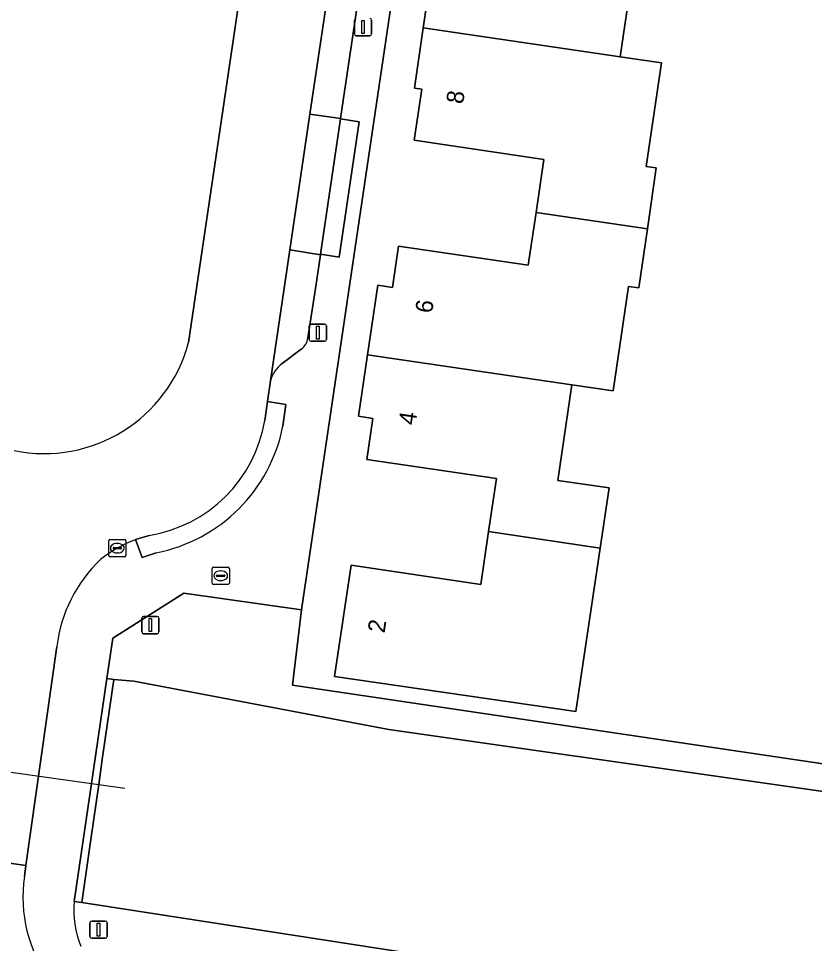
# Model space of a CAD drawing. Extents: x 164148 to 165261, y 382513 to 383432.
# Drawn here: x 164462.2 to 164508.4, y 382861.7 to 382915.4 of the extents above; entities that cross this region are included whole.
import ezdxf

# ---------------------------------------------------------------- set-up
doc = ezdxf.new("R2010")
doc.units = 0
for name, color, linetype in [('IMGEO_Duiker', 7, 'Continuous'), ('IMGEO_Erf', 7, 'Continuous'), ('IMGEO_Greppel_droge_sloot', 7, 'Continuous'), ('IMGEO_Groenvoorziening', 7, 'Continuous'), ('IMGEO_Kolk', 7, 'Continuous'), ('IMGEO_Lichtmast', 7, 'Continuous'), ('IMGEO_Muur', 7, 'Continuous'), ('IMGEO_Pand', 7, 'Continuous'), ('IMGEO_Pand_nummerreeks', 7, 'Continuous'), ('IMGEO_Parkeervlak_open', 7, 'Continuous'), ('IMGEO_Rijbaan_lokaal_open', 7, 'Continuous'), ('IMGEO_Rioolput', 7, 'Continuous'), ('IMGEO_Voetpad_open', 7, 'Continuous')]:
    doc.layers.add(name, color=color, linetype=linetype)

msp = doc.modelspace()

# ---------------------------------------------------------------- linework, layer by layer
at = {"layer": 'IMGEO_Duiker'}
msp.add_lwpolyline([(164452.014, 382872.996), (164453.522, 382872.784), (164453.949, 382872.723), (164466.481, 382870.957), (164466.901, 382870.898), (164468.418, 382870.684)], dxfattribs=at)
at = {"layer": 'IMGEO_Erf'}
msp.add_lwpolyline([(164536.67, 382930.425), (164544.133, 382980.726), (164542.913, 382982.243), (164519.298, 382985.737), (164495.986, 382989.176), (164494.523, 382988.072), (164478.67, 382881.048), (164478.137, 382876.668), (164527.73, 382869.322)], close=True, dxfattribs=at)
msp.add_lwpolyline([(164497.979, 382918.699), (164497.165, 382913.157), (164499.559, 382912.806), (164498.667, 382906.787), (164499.262, 382906.703), (164498.744, 382903.179), (164498.239, 382899.743), (164497.643, 382899.83), (164496.751, 382893.761), (164494.362, 382894.113), (164493.546, 382888.557), (164496.524, 382888.13), (164496.004, 382884.636), (164494.589, 382875.139), (164480.59, 382877.186), (164481.556, 382883.642), (164489.074, 382882.518), (164489.527, 382885.591), (164489.98, 382888.664), (164482.461, 382889.777), (164482.816, 382892.167), (164481.973, 382892.292), (164482.501, 382895.861), (164483.098, 382899.895), (164483.946, 382899.769), (164484.301, 382902.158), (164491.833, 382901.054), (164492.284, 382904.127), (164492.734, 382907.199), (164485.215, 382908.319), (164485.647, 382911.272), (164485.222, 382911.337), (164485.737, 382914.833), (164486.177, 382917.822)], dxfattribs=at)
at = {"layer": 'IMGEO_Greppel_droge_sloot'}
msp.add_lwpolyline([(164527.808, 382867.71), (164528.242, 382867.643), (164528.255, 382867.732), (164527.513, 382867.841), (164483.733, 382874.094), (164468.94, 382876.903), (164467.772, 382876.998), (164467.128, 382872.489), (164466.901, 382870.898), (164466.447, 382867.72), (164465.924, 382864.054), (164484.051, 382861.245), (164524.835, 382854.782), (164525.957, 382854.773), (164526.609, 382859.328), (164526.913, 382861.453), (164527.19, 382863.393)], close=True, dxfattribs=at)
at = {"layer": 'IMGEO_Groenvoorziening'}
for points in [[(164472.108, 382896.577), (164486.03, 382990.645)], [(164465.924, 382864.054), (164465.481, 382864.11)], [(164526.374, 382854.707), (164525.957, 382854.773), (164524.835, 382854.782), (164484.051, 382861.245), (164465.924, 382864.054)]]:
    msp.add_lwpolyline(points, dxfattribs=at)
msp.add_lwpolyline([(164478.137, 382876.668), (164478.67, 382881.048), (164471.849, 382882.015), (164467.712, 382879.403), (164467.374, 382877.067), (164467.772, 382876.998), (164468.94, 382876.903), (164483.733, 382874.094), (164527.513, 382867.841), (164527.73, 382869.322)], close=True, dxfattribs=at)
for centre, radius, start, end in [((164463.736, 382898.773), 8.655, 258.3612, 345.3007), ((164470.735, 382863.571), 5.282, 174.1455, 202.9355)]:
    msp.add_arc(centre, radius, start, end, dxfattribs=at)
at = {"layer": 'IMGEO_Kolk'}
for p, q in [((164467.478, 382884.202), (164467.478, 382885.054)), ((164467.553, 382885.128), (164468.405, 382885.128)), ((164467.966, 382884.908), (164467.991, 382884.908)), ((164468.479, 382885.054), (164468.479, 382884.202)), ((164467.737, 382884.622), (164467.737, 382884.634)), ((164468.175, 382884.585), (164467.777, 382884.585)), ((164467.78, 382884.671), (164468.178, 382884.671)), ((164467.989, 382884.348), (164467.964, 382884.348)), ((164468.221, 382884.634), (164468.221, 382884.622)), ((164468.405, 382884.128), (164467.553, 382884.128))]:
    msp.add_line(p, q, dxfattribs=at)
for points in [[(164467.478, 382884.202), (164467.478, 382885.054)], [(164467.553, 382885.128), (164468.405, 382885.128)], [(164468.479, 382885.054), (164468.479, 382884.202)], [(164468.405, 382884.128), (164467.553, 382884.128)]]:
    msp.add_lwpolyline(points, dxfattribs=at)
for centre, radius, start, end in [((164467.555, 382885.052), 0.0765, 91.552, 178.448), ((164467.555, 382885.052), 0.0765, 91.552, 178.448), ((164468.403, 382885.052), 0.0765, 1.552, 88.448), ((164468.403, 382885.052), 0.0765, 1.552, 88.448), ((164467.777, 382884.631), 0.0403, 85.8775, 175.7526), ((164467.774, 382884.621), 0.0366, 178.938, 274.7102), ((164468.178, 382884.628), 0.043, 264.8664, 352.4533), ((164468.182, 382884.633), 0.0386, 1.7309, 96.639), ((164467.555, 382884.204), 0.0765, 181.552, 268.448), ((164467.555, 382884.204), 0.0765, 181.552, 268.448), ((164468.403, 382884.204), 0.0765, 271.552, 358.448), ((164468.403, 382884.204), 0.0765, 271.552, 358.448)]:
    msp.add_arc(centre, radius, start, end, dxfattribs=at)
for centre, major_axis, ratio, start_param, end_param in [((164467.965, 382884.628), (-0.387, 0.002), 0.722429, 4.712389, 7.853982), ((164467.99, 382884.628), (-0.39, 0.002), 0.717154, 1.570796, 4.712389)]:
    msp.add_ellipse(centre, major_axis=major_axis, ratio=ratio, start_param=start_param, end_param=end_param, dxfattribs=at)
at = {"layer": 'IMGEO_Lichtmast'}
for p, q in [((164481.743, 382914.484), (164481.743, 382915.284)), ((164481.743, 382915.284), (164481.743, 382914.484)), ((164482.733, 382915.284), (164482.733, 382914.484)), ((164482.733, 382914.484), (164482.733, 382915.284)), ((164482.633, 382914.384), (164481.843, 382914.384)), ((164481.843, 382914.384), (164482.633, 382914.384)), ((164479.123, 382896.743), (164479.123, 382897.543)), ((164479.123, 382897.543), (164479.123, 382896.743)), ((164479.223, 382897.643), (164480.013, 382897.643)), ((164480.013, 382897.643), (164479.223, 382897.643)), ((164480.113, 382897.543), (164480.113, 382896.743)), ((164480.113, 382896.743), (164480.113, 382897.543)), ((164480.013, 382896.643), (164479.223, 382896.643)), ((164479.223, 382896.643), (164480.013, 382896.643)), ((164469.402, 382879.763), (164469.402, 382880.563)), ((164469.402, 382880.563), (164469.402, 382879.763)), ((164469.502, 382880.663), (164470.292, 382880.663)), ((164470.292, 382880.663), (164469.502, 382880.663)), ((164470.392, 382880.563), (164470.392, 382879.763)), ((164470.392, 382879.763), (164470.392, 382880.563)), ((164470.292, 382879.663), (164469.502, 382879.663)), ((164469.502, 382879.663), (164470.292, 382879.663)), ((164466.393, 382862.076), (164466.393, 382862.876)), ((164466.393, 382862.876), (164466.393, 382862.076)), ((164466.493, 382862.976), (164467.283, 382862.976)), ((164467.283, 382862.976), (164466.493, 382862.976)), ((164467.383, 382862.876), (164467.383, 382862.076)), ((164467.383, 382862.076), (164467.383, 382862.876)), ((164467.283, 382861.976), (164466.493, 382861.976)), ((164466.493, 382861.976), (164467.283, 382861.976))]:
    msp.add_line(p, q, dxfattribs=at)
for points in [[(164482.163, 382915.259), (164482.313, 382915.259), (164482.313, 382914.509), (164482.163, 382914.509), (164482.163, 382915.259)], [(164479.543, 382897.518), (164479.693, 382897.518), (164479.693, 382896.768), (164479.543, 382896.768), (164479.543, 382897.518)], [(164469.822, 382880.538), (164469.972, 382880.538), (164469.972, 382879.788), (164469.822, 382879.788), (164469.822, 382880.538)], [(164466.813, 382862.851), (164466.963, 382862.851), (164466.963, 382862.101), (164466.813, 382862.101), (164466.813, 382862.851)]]:
    msp.add_lwpolyline(points, dxfattribs=at)
for centre, start, end in [((164481.843, 382915.284), 90, 180), ((164481.843, 382915.284), 90, 180), ((164482.633, 382915.284), 0, 90), ((164482.633, 382915.284), 360, 90), ((164481.843, 382914.484), 180, 270), ((164481.843, 382914.484), 180, 270), ((164482.633, 382914.484), 270, 0), ((164482.633, 382914.484), 270, 0), ((164479.223, 382897.543), 90, 180), ((164479.223, 382897.543), 90, 180), ((164480.013, 382897.543), 0, 90), ((164480.013, 382897.543), 360, 90), ((164479.223, 382896.743), 180, 270), ((164479.223, 382896.743), 180, 270), ((164480.013, 382896.743), 270, 0), ((164480.013, 382896.743), 270, 0), ((164469.502, 382880.563), 90, 180), ((164469.502, 382880.563), 90, 180), ((164470.292, 382880.563), 0, 90), ((164470.292, 382880.563), 360, 90), ((164469.502, 382879.763), 180, 270), ((164469.502, 382879.763), 180, 270), ((164470.292, 382879.763), 270, 0), ((164470.292, 382879.763), 270, 0), ((164466.493, 382862.876), 90, 180), ((164466.493, 382862.876), 90, 180), ((164467.283, 382862.876), 0, 90), ((164467.283, 382862.876), 360, 90), ((164466.493, 382862.076), 180, 270), ((164466.493, 382862.076), 180, 270), ((164467.283, 382862.076), 270, 0), ((164467.283, 382862.076), 270, 0)]:
    msp.add_arc(centre, 0.1, start, end, dxfattribs=at)
at = {"layer": 'IMGEO_Muur'}
msp.add_lwpolyline([(164466.901, 382870.898), (164467.128, 382872.489), (164467.772, 382876.998), (164467.374, 382877.067), (164466.481, 382870.957), (164465.481, 382864.11), (164465.924, 382864.054), (164466.447, 382867.72)], close=True, dxfattribs=at)
at = {"layer": 'IMGEO_Pand'}
for points in [[(164497.979, 382918.699), (164500.947, 382918.264), (164501.455, 382921.725), (164495.029, 382922.675), (164494.577, 382919.612), (164487.065, 382920.724), (164486.631, 382917.756), (164486.177, 382917.822), (164485.737, 382914.833), (164497.165, 382913.157)], [(164499.559, 382912.806), (164497.165, 382913.157), (164485.737, 382914.833), (164485.222, 382911.337), (164485.647, 382911.272), (164485.215, 382908.319), (164492.734, 382907.199), (164492.284, 382904.127), (164498.744, 382903.179), (164499.262, 382906.703), (164498.667, 382906.787)], [(164497.643, 382899.83), (164498.239, 382899.743), (164498.744, 382903.179), (164492.284, 382904.127), (164491.833, 382901.054), (164484.301, 382902.158), (164483.946, 382899.769), (164483.098, 382899.895), (164482.501, 382895.861), (164494.362, 382894.113), (164496.751, 382893.761)], [(164494.362, 382894.113), (164482.501, 382895.861), (164481.973, 382892.292), (164482.816, 382892.167), (164482.461, 382889.777), (164489.98, 382888.664), (164489.527, 382885.591), (164496.004, 382884.636), (164496.524, 382888.13), (164493.546, 382888.557)], [(164496.004, 382884.636), (164489.527, 382885.591), (164489.074, 382882.518), (164481.556, 382883.642), (164480.59, 382877.186), (164494.589, 382875.139)]]:
    msp.add_lwpolyline(points, close=True, dxfattribs=at)
at = {"layer": 'IMGEO_Parkeervlak_open'}
msp.add_lwpolyline([(164482.551, 382920.561), (164480.788, 382920.832), (164479.16, 382909.83), (164480.931, 382909.577)], close=True, dxfattribs=at)
for points in [[(164479.764, 382901.668), (164477.996, 382901.958), (164476.868, 382894.336)], [(164479.045, 382896.841), (164479.476, 382899.714), (164479.764, 382901.668)], [(164477.551, 382895.355), (164478.65, 382896.182)]]:
    msp.add_lwpolyline(points, dxfattribs=at)
for centre, radius, start, end in [((164478.079, 382896.972), 0.975, 305.8664, 352.2573), ((164478.751, 382893.812), 1.955, 127.8789, 164.456)]:
    msp.add_arc(centre, radius, start, end, dxfattribs=at)
at = {"layer": 'IMGEO_Rijbaan_lokaal_open'}
for points in [[(164486.178, 382991.604), (164486.03, 382990.645), (164472.108, 382896.577)], [(164476.532, 382892.042), (164476.696, 382893.15), (164476.868, 382894.336), (164477.996, 382901.958), (164479.16, 382909.83), (164480.788, 382920.832), (164481.951, 382928.698), (164483.373, 382938.31), (164483.514, 382939.266), (164484.677, 382947.121), (164486.275, 382957.923), (164487.446, 382965.833), (164488.991, 382976.277)], [(164469.039, 382885.122), (164469.821, 382885.37)], [(164461.696, 382881.26), (164459.552, 382866.638), (164462.678, 382866.2), (164464.472, 382878.91)], [(164462.678, 382866.2), (164459.552, 382866.638), (164458.935, 382862.431)], [(164462.587, 382865.559), (164462.678, 382866.2)]]:
    msp.add_lwpolyline(points, dxfattribs=at)
for centre, radius, start, end in [((164463.736, 382898.773), 8.655, 258.3612, 345.3007), ((164468.536, 382893.374), 8.106, 279.121, 350.5451), ((164471.616, 382878.209), 7.377, 110.4412, 128.6591), ((164472.707, 382877.949), 8.291, 133.4338, 173.3456), ((164470.627, 382864.363), 8.128, 171.5391, 259.6623)]:
    msp.add_arc(centre, radius, start, end, dxfattribs=at)
at = {"layer": 'IMGEO_Rioolput'}
for p, q in [((164473.48, 382882.6), (164473.48, 382883.452)), ((164473.555, 382883.526), (164474.407, 382883.526)), ((164473.968, 382883.306), (164473.993, 382883.306)), ((164474.481, 382883.452), (164474.481, 382882.6)), ((164473.739, 382883.02), (164473.739, 382883.032)), ((164474.177, 382882.983), (164473.779, 382882.983)), ((164473.782, 382883.069), (164474.18, 382883.069)), ((164473.991, 382882.746), (164473.966, 382882.746)), ((164474.223, 382883.032), (164474.223, 382883.02)), ((164474.407, 382882.526), (164473.555, 382882.526))]:
    msp.add_line(p, q, dxfattribs=at)
for points in [[(164473.48, 382882.6), (164473.48, 382883.452)], [(164473.555, 382883.526), (164474.407, 382883.526)], [(164474.481, 382883.452), (164474.481, 382882.6)], [(164474.407, 382882.526), (164473.555, 382882.526)]]:
    msp.add_lwpolyline(points, dxfattribs=at)
for centre, radius, start, end in [((164473.557, 382883.45), 0.0765, 91.552, 178.448), ((164473.557, 382883.45), 0.0765, 91.552, 178.448), ((164474.405, 382883.45), 0.0765, 1.552, 88.448), ((164474.405, 382883.45), 0.0765, 1.552, 88.448), ((164473.779, 382883.029), 0.0403, 85.8775, 175.7526), ((164473.776, 382883.019), 0.0366, 178.938, 274.7102), ((164474.18, 382883.026), 0.043, 264.8664, 352.4533), ((164474.184, 382883.031), 0.0386, 1.7309, 96.639), ((164473.557, 382882.602), 0.0765, 181.552, 268.448), ((164473.557, 382882.602), 0.0765, 181.552, 268.448), ((164474.405, 382882.602), 0.0765, 271.552, 358.448), ((164474.405, 382882.602), 0.0765, 271.552, 358.448)]:
    msp.add_arc(centre, radius, start, end, dxfattribs=at)
for centre, major_axis, ratio, start_param, end_param in [((164473.967, 382883.026), (-0.387, 0.002), 0.722429, 4.712389, 7.853982), ((164473.992, 382883.026), (-0.39, 0.002), 0.717154, 1.570796, 4.712389)]:
    msp.add_ellipse(centre, major_axis=major_axis, ratio=ratio, start_param=start_param, end_param=end_param, dxfattribs=at)
at = {"layer": 'IMGEO_Voetpad_open'}
for points in [[(164465.481, 382864.11), (164466.481, 382870.957), (164467.374, 382877.067), (164467.712, 382879.403), (164471.849, 382882.015), (164478.67, 382881.048), (164494.523, 382988.072)], [(164490.746, 382975.998), (164489.205, 382965.585), (164490.303, 382965.43), (164489.157, 382957.572), (164488.043, 382957.727), (164488.033, 382957.664), (164486.455, 382946.998), (164487.539, 382946.837), (164486.391, 382938.884), (164485.273, 382939.013), (164485.123, 382937.996), (164483.718, 382928.469), (164483.71, 382928.42), (164484.794, 382928.268), (164483.654, 382920.435), (164482.551, 382920.561), (164480.931, 382909.577), (164480.928, 382909.558), (164482.007, 382909.387), (164480.864, 382901.519), (164479.769, 382901.698), (164479.764, 382901.668), (164479.476, 382899.714), (164479.045, 382896.841)], [(164478.65, 382896.182), (164477.551, 382895.355)], [(164476.868, 382894.336), (164476.696, 382893.15), (164477.766, 382892.971), (164477.586, 382891.712)], [(164476.696, 382893.15), (164476.532, 382892.042)], [(164477.586, 382891.712), (164477.766, 382892.971), (164476.696, 382893.15)], [(164469.821, 382885.37), (164469.039, 382885.122), (164469.416, 382884.094), (164470.227, 382884.359)], [(164470.227, 382884.359), (164469.416, 382884.094), (164469.039, 382885.122)], [(164464.472, 382878.91), (164462.678, 382866.2), (164462.587, 382865.559)]]:
    msp.add_lwpolyline(points, dxfattribs=at)
for points in [[(164480.928, 382909.558), (164480.931, 382909.577), (164479.16, 382909.83), (164477.996, 382901.958), (164479.764, 382901.668), (164479.769, 382901.698)], [(164480.928, 382909.558), (164479.769, 382901.698), (164480.864, 382901.519), (164482.007, 382909.387)]]:
    msp.add_lwpolyline(points, close=True, dxfattribs=at)
for centre, radius, start, end in [((164478.079, 382896.972), 0.975, 305.8664, 352.2573), ((164478.751, 382893.812), 1.955, 127.8789, 164.456), ((164468.536, 382893.374), 8.106, 279.121, 350.5451), ((164468.439, 382893.507), 9.322, 281.0588, 348.8945), ((164468.439, 382893.507), 9.322, 281.0588, 348.8945), ((164471.616, 382878.209), 7.377, 110.4412, 128.6591), ((164472.707, 382877.949), 8.291, 133.4338, 173.3456), ((164470.627, 382864.363), 8.128, 171.5391, 259.6623), ((164470.735, 382863.571), 5.282, 174.1455, 202.9355)]:
    msp.add_arc(centre, radius, start, end, dxfattribs=at)

# ---------------------------------------------------------------- texts
at = {"layer": 'IMGEO_Pand_nummerreeks'}
for s, rotation, p in [('8', 81.6751, (164488.043, 382910.384)), ('6', 81.5491, (164486.245, 382898.232)), ('4', 81.5491, (164485.28, 382891.735)), ('2', 81.4918, (164483.489, 382879.669))]:
    msp.add_text(s, height=1, rotation=rotation, dxfattribs=at).set_placement(p)

doc.saveas('drawing.dxf')
